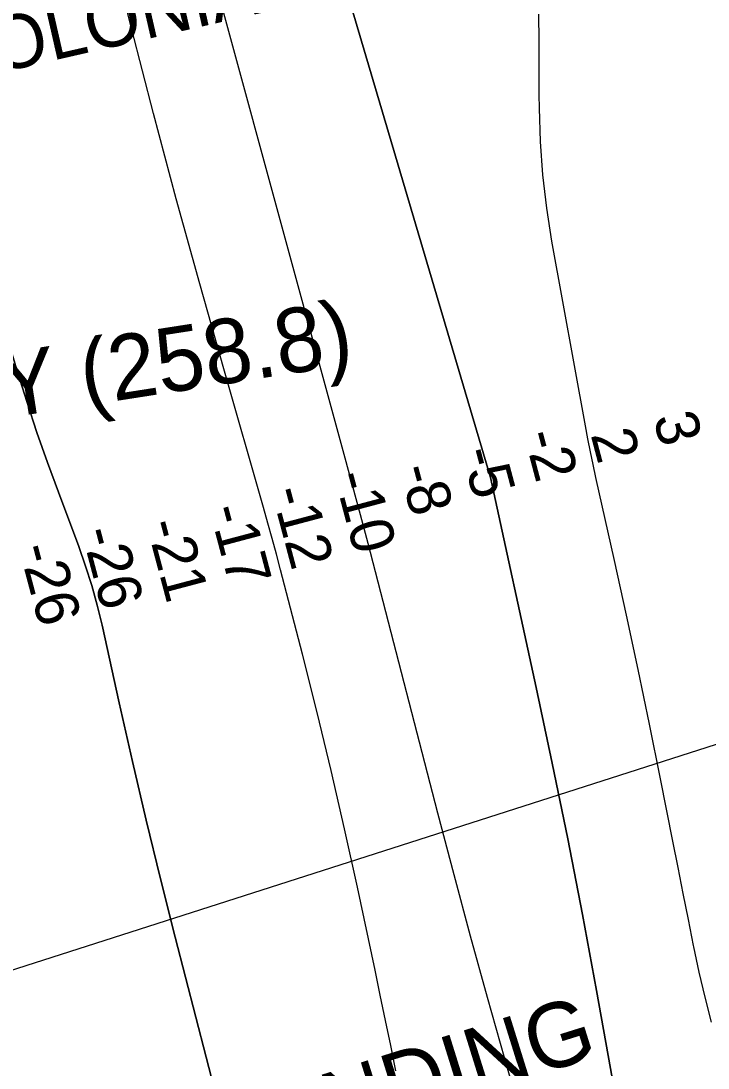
# Model space of a CAD drawing. Extents: x 3263578 to 3301413, y 764927 to 798602.
# Drawn here: x 3277071 to 3278134, y 789786 to 791406 of the extents above; entities that cross this region are included whole.
import ezdxf

# ---------------------------------------------------------------- set-up
doc = ezdxf.new("R2010")
doc.units = 0
for name, color, linetype in [('V-CHAN-NAID', 7, 'Continuous'), ('V-RIVR-RANG', 7, 'Continuous'), ('V-TOPO-DPTH', 7, 'Continuous'), ('V-TOPO-GNAM-IDEN', 7, 'Continuous'), ('V-TOPO-MINR', 7, 'Continuous'), ('V-UTIL-IDEN', 7, 'Continuous'), ('V-UTIL-LINE', 7, 'Continuous')]:
    doc.layers.add(name, color=color, linetype=linetype)

msp = doc.modelspace()

# ---------------------------------------------------------------- linework, layer by layer
at = {"layer": 'V-TOPO-DPTH'}
for points in [[(3277392.7, 794016.2), (3277320.6, 793028.3), (3277390.1, 792289.5), (3277394.1, 792247.5), (3277398.2, 792205.5), (3277402.5, 792163.5), (3277406.8, 792121.5), (3277411.9, 792079.7), (3277418.1, 792038), (3277425.9, 791996.6), (3277434.8, 791955.3), (3277464.4, 791828.7), (3277466.2, 791821.3), (3277468.1, 791813.9), (3277470.2, 791806.5), (3277472.3, 791799.2), (3277797.1, 790699.3), (3277867.8, 790374.8), (3277892.6, 790257.8), (3277916.6, 790140.7), (3277939.3, 790023.3), (3277961.1, 789905.7), (3278003.5, 789670.3), (3278172, 789173.4)], [(3278172, 789173.4), (3278003.5, 789670.3), (3277961.1, 789905.7), (3277939.3, 790023.3), (3277916.6, 790140.7), (3277892.6, 790257.8), (3277867.8, 790374.8), (3277797.1, 790699.3), (3277472.3, 791799.2), (3277470.2, 791806.5), (3277468.1, 791813.9), (3277466.2, 791821.3), (3277464.4, 791828.7), (3277434.8, 791955.3), (3277425.9, 791996.6), (3277418.1, 792038), (3277411.9, 792079.7), (3277406.8, 792121.5), (3277402.5, 792163.5), (3277398.2, 792205.5), (3277394.1, 792247.5), (3277390.1, 792289.5), (3277320.6, 793028.3), (3277392.7, 794016.2)], [(3277650.5, 789781.6), (3277642.6, 789820.6), (3277634.7, 789859.5), (3277626.6, 789898.5), (3277618.4, 789937.4), (3277591.2, 790065.7), (3277571.4, 790156.1), (3277550.7, 790246.3), (3277528.9, 790336.2), (3277506.3, 790426), (3277472.3, 790556.9), (3277465.9, 790581), (3277459.5, 790605.1), (3277452.8, 790629.1), (3277446, 790653.1), (3277384.3, 790867.6), (3277347.2, 790999), (3277310.9, 791130.6), (3277275.9, 791262.5), (3277241.6, 791394.6), (3277163.1, 791703.6)], [(3277650.5, 789781.6), (3277642.6, 789820.6), (3277634.7, 789859.5), (3277626.6, 789898.5), (3277618.4, 789937.4), (3277591.2, 790065.7), (3277571.4, 790156.1), (3277550.7, 790246.3), (3277528.9, 790336.2), (3277506.3, 790426), (3277472.3, 790556.9), (3277465.9, 790581), (3277459.5, 790605.1), (3277452.8, 790629.1), (3277446, 790653.1), (3277384.3, 790867.6), (3277347.2, 790999), (3277310.9, 791130.6), (3277275.9, 791262.5), (3277241.6, 791394.6), (3277163.1, 791703.6)], [(3276877.9, 791657.8), (3277015.2, 791052), (3277026.5, 791004.3), (3277038.6, 790956.8), (3277051.7, 790909.5), (3277065.5, 790862.5), (3277080.2, 790815.7), (3277095.5, 790769.1), (3277111.8, 790722.9), (3277128.6, 790676.8), (3277160.2, 790592.6), (3277170.8, 790562.6), (3277180.5, 790532.4), (3277188.8, 790501.8), (3277196.3, 790470.9), (3277222.7, 790351), (3277243.2, 790260.1), (3277264.4, 790169.3), (3277286.5, 790078.8), (3277309.3, 789988.4), (3277453.1, 789431.5)], [(3276877.9, 791657.8), (3277015.2, 791052), (3277026.5, 791004.3), (3277038.6, 790956.8), (3277051.7, 790909.5), (3277065.5, 790862.5), (3277080.2, 790815.7), (3277095.5, 790769.1), (3277111.8, 790722.9), (3277128.6, 790676.8), (3277160.2, 790592.6), (3277170.8, 790562.6), (3277180.5, 790532.4), (3277188.8, 790501.8), (3277196.3, 790470.9), (3277222.7, 790351), (3277243.2, 790260.1), (3277264.4, 790169.3), (3277286.5, 790078.8), (3277309.3, 789988.4), (3277453.1, 789431.5)]]:
    msp.add_lwpolyline(points, dxfattribs=at)
at = {"layer": 'V-TOPO-MINR'}
for points in [[(3278172, 789173.4), (3278003.5, 789670.3), (3277961.1, 789905.7), (3277939.3, 790023.3), (3277916.6, 790140.7), (3277892.6, 790257.8), (3277867.8, 790374.8), (3277797.1, 790699.3), (3277472.3, 791799.2), (3277470.2, 791806.5), (3277468.1, 791813.9), (3277466.2, 791821.3), (3277464.4, 791828.7), (3277434.8, 791955.3), (3277425.9, 791996.6), (3277418.1, 792038), (3277411.9, 792079.7), (3277406.8, 792121.5), (3277402.5, 792163.5), (3277398.2, 792205.5), (3277394.1, 792247.5), (3277390.1, 792289.5), (3277320.6, 793028.3), (3277392.7, 794016.2)], [(3277861.3, 789652.5), (3277819.1, 789800.1), (3277792.4, 789894.9), (3277766.2, 789989.9), (3277740.7, 790085), (3277715.7, 790180.3), (3277619.1, 790553.4), (3277607.6, 790597.6), (3277596, 790641.7), (3277584.2, 790685.7), (3277572.3, 790729.7), (3277288.4, 791770)], [(3277650.5, 789781.6), (3277642.6, 789820.6), (3277634.7, 789859.5), (3277626.6, 789898.5), (3277618.4, 789937.4), (3277591.2, 790065.7), (3277571.4, 790156.1), (3277550.7, 790246.3), (3277528.9, 790336.2), (3277506.3, 790426), (3277472.3, 790556.9), (3277465.9, 790581), (3277459.5, 790605.1), (3277452.8, 790629.1), (3277446, 790653.1), (3277384.3, 790867.6), (3277347.2, 790999), (3277310.9, 791130.6), (3277275.9, 791262.5), (3277241.6, 791394.6), (3277163.1, 791703.6)], [(3277453.1, 789431.5), (3277309.3, 789988.4), (3277286.5, 790078.8), (3277264.4, 790169.3), (3277243.2, 790260.1), (3277222.7, 790351), (3277196.3, 790470.9), (3277188.8, 790501.8), (3277180.5, 790532.4), (3277170.8, 790562.6), (3277160.2, 790592.6), (3277128.6, 790676.8), (3277111.8, 790722.9), (3277095.5, 790769.1), (3277080.2, 790815.7), (3277065.5, 790862.5), (3277051.7, 790909.5), (3277038.6, 790956.8), (3277026.5, 791004.3), (3277015.2, 791052), (3276877.9, 791657.8)], [(3278138.9, 789856.9), (3278129, 789895.5), (3278120, 789934.4), (3278111.7, 789973.3), (3278111.2, 789975.6), (3278103.1, 790015.9), (3278095.1, 790056.1), (3278087.1, 790096.4), (3278079.1, 790136.7), (3278060, 790233.3), (3278042.9, 790317.8), (3278025.4, 790402.3), (3278007.4, 790486.7), (3277988.9, 790570.9), (3277960.2, 790699.6), (3277955.9, 790719.5), (3277951.7, 790739.4), (3277947.8, 790759.4), (3277944, 790779.4), (3277891.9, 791065.1), (3277883.9, 791116.3), (3277877.8, 791167.6), (3277874.3, 791219.2), (3277872.6, 791271), (3277872.5, 791291.5), (3277872.3, 791333.2), (3277872.1, 791374.8), (3277871.9, 791416.5)]]:
    msp.add_lwpolyline(points, dxfattribs=at)
at = {"layer": 'V-UTIL-LINE'}
msp.add_lwpolyline([(3276105.2, 789632.5), (3281091.1, 791231.4)], dxfattribs=at)

# ---------------------------------------------------------------- texts
at = {"layer": 'V-CHAN-NAID'}
msp.add_text('GRAND BAY (258.8)', height=100, rotation=8.8807, dxfattribs=at).set_placement((3276354.9, 790683.1))
at = {"layer": 'V-RIVR-RANG'}
for s, p in [('3', (3278048.3, 790792)), ('2', (3277951.7, 790766)), ('-2', (3277848.2, 790766)), ('-5', (3277751.8, 790739.4)), ('-8', (3277655.4, 790712.9)), ('-10', (3277554.7, 790702.4)), ('-12', (3277457.6, 790678.7)), ('-17', (3277361.5, 790650.7)), ('-21', (3277264.1, 790627.9)), ('-26', (3277163.8, 790615.9)), ('-26', (3277067.1, 790590.4))]:
    msp.add_text(s, height=67, rotation=284.8715, dxfattribs=at).set_placement(p)
at = {"layer": 'V-TOPO-GNAM-IDEN'}
msp.add_text('GRAND BAY LANDING', height=100, rotation=17.3212, dxfattribs=at).set_placement((3276611.7, 789382.6))
at = {"layer": 'V-UTIL-IDEN'}
msp.add_text('COLONIAL PIPELINE CO.', height=83, rotation=12.8907, dxfattribs=at).set_placement((3276956.1, 791306.9))

doc.saveas('drawing.dxf')
